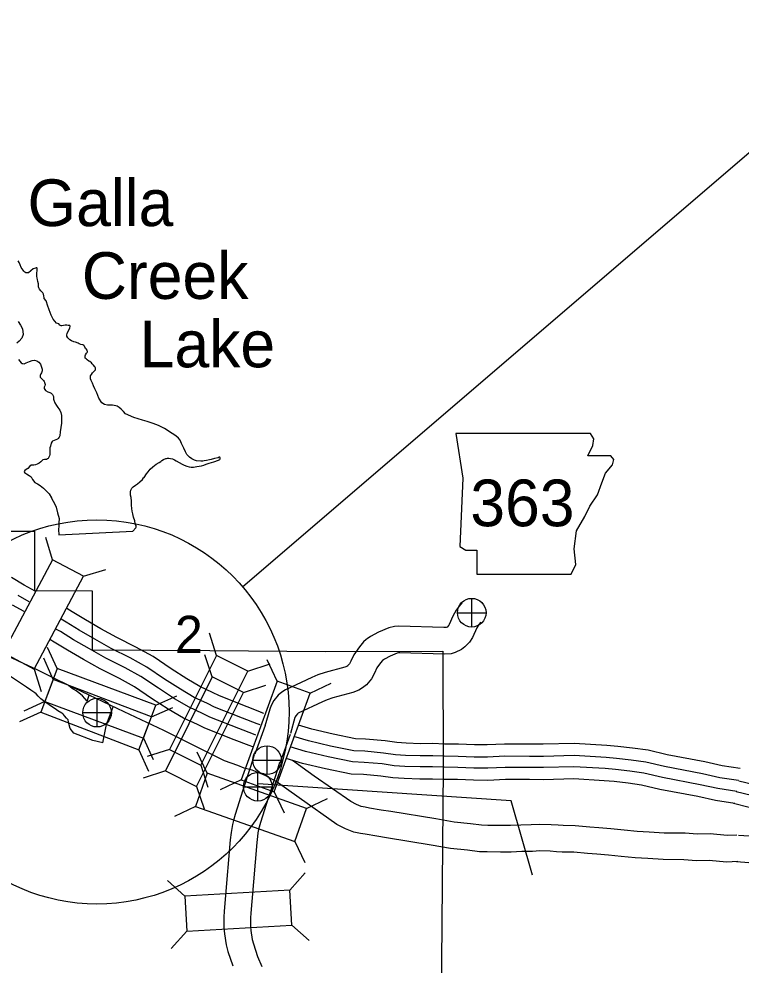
# Model space of a CAD drawing. Extents: x 1374139 to 1377472, y 1168351 to 1170484.
# Drawn here: x 1374655.3 to 1374736.9, y 1169975.1 to 1170082.1 of the extents above; entities that cross this region are included whole.
import ezdxf

# ---------------------------------------------------------------- set-up
doc = ezdxf.new("R2010")
doc.units = 0
doc.layers.add('15', color=7, linetype='Continuous')
doc.layers.add('Default', color=7, linetype='Continuous')

msp = doc.modelspace()

# ---------------------------------------------------------------- linework, layer by layer
at = {"layer": '15'}
msp.add_line((1374910.7, 1170215.21), (1374680.58, 1170017.86), dxfattribs=at)
msp.add_circle((1374664.1, 1170003.73), 21.71, dxfattribs=at)
at = {"layer": 'Default'}
for p, q in [((1374659.09, 1170020.93), (1374658.32, 1170023.46)), ((1374662.59, 1170019.07), (1374665.11, 1170019.84)), ((1374706.46, 1170013.33), (1374706.46, 1170016.58)), ((1374704.84, 1170014.95), (1374708.09, 1170014.95)), ((1374677.63, 1170010.11), (1374676.81, 1170012.62)), ((1374659.61, 1170008.63), (1374658.51, 1170011.03)), ((1374659.16, 1170007.41), (1374658.09, 1170009.82)), ((1374677.14, 1170007.69), (1374676.31, 1170010.2)), ((1374684.47, 1170007.22), (1374683.35, 1170009.61)), ((1374657.01, 1170008.58), (1374657.78, 1170006.06)), ((1374681.17, 1170008.33), (1374683.68, 1170009.16)), ((1374680.68, 1170005.92), (1374683.19, 1170006.76)), ((1374688.19, 1170005.87), (1374690.58, 1170006.99)), ((1374664.11, 1170002.03), (1374664.11, 1170005.28)), ((1374670.74, 1170004.48), (1374673.14, 1170005.57)), ((1374658.22, 1170004.92), (1374655.82, 1170003.82)), ((1374670.26, 1170003.16), (1374672.67, 1170004.24)), ((1374657.75, 1170003.71), (1374655.34, 1170002.63)), ((1374662.49, 1170003.65), (1374665.74, 1170003.65)), ((1374669.36, 1170000.77), (1374670.45, 1169998.36)), ((1374683.33, 1169996.65), (1374683.33, 1169999.9)), ((1374668.84, 1169999.46), (1374669.92, 1169997.05)), ((1374672.29, 1169999.5), (1374669.78, 1169998.68)), ((1374676.57, 1169996.8), (1374675.44, 1169999.18)), ((1374681.7, 1169998.28), (1374684.95, 1169998.28)), ((1374671.83, 1169997.07), (1374669.32, 1169996.24)), ((1374675.83, 1169997.72), (1374676.65, 1169995.22)), ((1374682.28, 1169993.66), (1374682.28, 1169996.91)), ((1374680.41, 1169996.06), (1374678.02, 1169994.94)), ((1374675.37, 1169995.3), (1374676.2, 1169992.79)), ((1374680.66, 1169995.28), (1374683.91, 1169995.28)), ((1374684.14, 1169994.7), (1374685.25, 1169992.31)), ((1374687.77, 1169992.83), (1374690.15, 1169993.96)), ((1374675.25, 1169993.06), (1374672.87, 1169991.93)), ((1374686.45, 1169989.09), (1374687.58, 1169986.71)), ((1374685.89, 1169983.59), (1374687.65, 1169985.56)), ((1374674.03, 1169982.92), (1374672.06, 1169984.68)), ((1374686.12, 1169979.63), (1374688.09, 1169977.88)), ((1374674.26, 1169978.96), (1374672.5, 1169976.99))]:
    msp.add_line(p, q, dxfattribs=at)
for points in [[(1374657.35, 1170053.58), (1374657.34, 1170053.71), (1374657.36, 1170053.8), (1374657.35, 1170053.88), (1374657.29, 1170053.92), (1374657.21, 1170053.93), (1374657.16, 1170053.91), (1374656.88, 1170053.81), (1374656.37, 1170053.37), (1374656.3, 1170053.35), (1374656.16, 1170053.35), (1374656.05, 1170053.38), (1374655.94, 1170053.43), (1374655.84, 1170053.54), (1374655.75, 1170053.68), (1374655.55, 1170053.97), (1374655.43, 1170054.29), (1374655.31, 1170054.55), (1374655.2, 1170054.74)], [(1374666.06, 1170038.38), (1374665.86, 1170038.42), (1374665.55, 1170038.42), (1374665.31, 1170038.41), (1374664.97, 1170038.5), (1374664.65, 1170038.67), (1374664.33, 1170039.21), (1374664.08, 1170039.79), (1374663.85, 1170040.24), (1374663.7, 1170040.6), (1374663.58, 1170040.89), (1374663.44, 1170041.18), (1374663.38, 1170041.4), (1374663.38, 1170041.71), (1374663.47, 1170041.89), (1374663.58, 1170042.07), (1374663.65, 1170042.12), (1374663.72, 1170042.18), (1374663.78, 1170042.25), (1374663.84, 1170042.3), (1374663.9, 1170042.38), (1374663.92, 1170042.42), (1374663.95, 1170042.52), (1374663.94, 1170042.64), (1374663.88, 1170042.71), (1374663.85, 1170042.74), (1374663.7, 1170042.92), (1374663.62, 1170043), (1374663.55, 1170043.1), (1374663.48, 1170043.2), (1374663.29, 1170043.33), (1374663.18, 1170043.39), (1374663.01, 1170043.53), (1374662.87, 1170043.65), (1374662.78, 1170043.74), (1374662.77, 1170043.84), (1374662.78, 1170043.99), (1374662.8, 1170044.11), (1374662.9, 1170044.27), (1374662.99, 1170044.35), (1374663.03, 1170044.45), (1374662.99, 1170044.64), (1374662.88, 1170044.79), (1374662.82, 1170044.86), (1374662.74, 1170044.98), (1374662.69, 1170045.07), (1374662.6, 1170045.16), (1374662.51, 1170045.22), (1374662.27, 1170045.28), (1374662.09, 1170045.34), (1374661.98, 1170045.43), (1374661.68, 1170045.53), (1374661.48, 1170045.58), (1374661.23, 1170045.67), (1374661.05, 1170045.78), (1374660.92, 1170045.89), (1374660.79, 1170046.01), (1374660.68, 1170046.2), (1374660.68, 1170046.34), (1374660.74, 1170046.56), (1374660.99, 1170047.03), (1374661.04, 1170047.15), (1374661.08, 1170047.29), (1374661.04, 1170047.4), (1374660.93, 1170047.42), (1374660.83, 1170047.43), (1374660.71, 1170047.44), (1374660.51, 1170047.44), (1374660.33, 1170047.4), (1374660.12, 1170047.38), (1374660.04, 1170047.39), (1374659.91, 1170047.47), (1374659.8, 1170047.59), (1374659.52, 1170047.69), (1374659.32, 1170047.9), (1374659.14, 1170048.12), (1374658.93, 1170048.6), (1374658.69, 1170049.2), (1374658.52, 1170049.73), (1374658.4, 1170050.08), (1374658.36, 1170050.22), (1374658.15, 1170050.48), (1374658.13, 1170050.56), (1374658.09, 1170050.75), (1374658.05, 1170050.95), (1374657.99, 1170051.11), (1374657.91, 1170051.19), (1374657.86, 1170051.22), (1374657.74, 1170051.35), (1374657.61, 1170051.52), (1374657.54, 1170051.68), (1374657.51, 1170051.78), (1374657.48, 1170052.02), (1374657.48, 1170052.14), (1374657.43, 1170052.39), (1374657.37, 1170052.62), (1374657.34, 1170052.78), (1374657.31, 1170052.98), (1374657.3, 1170053.23), (1374657.3, 1170053.38), (1374657.35, 1170053.58)], [(1374655.18, 1170047.87), (1374655.45, 1170047.47), (1374655.67, 1170047.02), (1374655.76, 1170046.41), (1374655.61, 1170046), (1374655.31, 1170045.65), (1374655.03, 1170045.43)], [(1374655.22, 1170043.56), (1374655.37, 1170043.39), (1374655.54, 1170043.2), (1374655.64, 1170043.13), (1374655.73, 1170043.11), (1374655.87, 1170043.1), (1374656.11, 1170043.2), (1374656.49, 1170043.35), (1374656.79, 1170043.46), (1374657.04, 1170043.48), (1374657.32, 1170043.42), (1374657.52, 1170043.28), (1374657.7, 1170043.03), (1374657.78, 1170042.83), (1374657.89, 1170042.47), (1374657.89, 1170042.3), (1374657.83, 1170042.08), (1374657.76, 1170041.94), (1374657.69, 1170041.78), (1374657.67, 1170041.72), (1374657.67, 1170041.64), (1374657.69, 1170041.56), (1374657.78, 1170041.45), (1374657.89, 1170041.36), (1374658.05, 1170041.21), (1374658.13, 1170041.09), (1374658.16, 1170041.02), (1374658.18, 1170040.99), (1374658.22, 1170040.84), (1374658.23, 1170040.75), (1374658.19, 1170040.61), (1374658.14, 1170040.44), (1374658.13, 1170040.37), (1374658.14, 1170040.31), (1374658.22, 1170040.17), (1374658.29, 1170040.08), (1374658.54, 1170039.93), (1374658.78, 1170039.83), (1374658.91, 1170039.76), (1374659.08, 1170039.63), (1374659.18, 1170039.4), (1374659.19, 1170039.22), (1374659.2, 1170039.08), (1374659.22, 1170038.96), (1374659.35, 1170038.67), (1374659.52, 1170038.38), (1374659.69, 1170038.15), (1374659.89, 1170037.83), (1374660.02, 1170037.59), (1374660.11, 1170037.24), (1374660.08, 1170036.37), (1374659.95, 1170035.38), (1374659.9, 1170034.96), (1374659.82, 1170034.78), (1374659.71, 1170034.65), (1374659.63, 1170034.57), (1374659.45, 1170034.49), (1374659.26, 1170034.41), (1374659.09, 1170034.34), (1374659.02, 1170034.29), (1374658.94, 1170034.13), (1374658.84, 1170033.79), (1374658.79, 1170033.58), (1374658.78, 1170033.37), (1374658.76, 1170033.05), (1374658.76, 1170032.85), (1374658.74, 1170032.7), (1374658.67, 1170032.52), (1374658.57, 1170032.38), (1374658.5, 1170032.33), (1374658.38, 1170032.28), (1374658.28, 1170032.26)], [(1374635.04, 1170037.43), (1374636.08, 1170037.43), (1374636.01, 1170037.28), (1374637.38, 1170036.89), (1374637.59, 1170037.42), (1374643.93, 1170037.4), (1374650.53, 1170037.38), (1374650.48, 1170030.78), (1374650.43, 1170024.18), (1374657.03, 1170024.15), (1374657.04, 1170017.47)], [(1374668.16, 1170024.17), (1374668.5, 1170024.55), (1374668.53, 1170024.6), (1374668.53, 1170024.69), (1374668.52, 1170024.81), (1374668.43, 1170024.99), (1374668.37, 1170025.34), (1374668.22, 1170025.73), (1374668.16, 1170026.11), (1374668.09, 1170026.43), (1374668.06, 1170026.73), (1374668.01, 1170027.11), (1374667.99, 1170027.54), (1374667.95, 1170027.98), (1374667.91, 1170028.24), (1374667.91, 1170028.47), (1374667.9, 1170028.63), (1374667.93, 1170028.81), (1374668.03, 1170029.01), (1374668.21, 1170029.18), (1374668.46, 1170029.37), (1374668.7, 1170029.52), (1374668.96, 1170029.73), (1374669.24, 1170030), (1374669.37, 1170030.19), (1374669.42, 1170030.25), (1374669.69, 1170030.63), (1374669.88, 1170030.89), (1374670.11, 1170031.19), (1374670.41, 1170031.44), (1374670.61, 1170031.59), (1374670.81, 1170031.73), (1374671.12, 1170031.93), (1374671.33, 1170032.06), (1374671.45, 1170032.16), (1374671.63, 1170032.27), (1374671.88, 1170032.37), (1374671.97, 1170032.39), (1374672.09, 1170032.41), (1374672.24, 1170032.42), (1374672.42, 1170032.38), (1374672.64, 1170032.34), (1374672.87, 1170032.23), (1374673.07, 1170032.13), (1374673.39, 1170031.94), (1374673.72, 1170031.75), (1374673.95, 1170031.64), (1374674.26, 1170031.51), (1374674.51, 1170031.44), (1374674.76, 1170031.41), (1374675.02, 1170031.41), (1374675.39, 1170031.47), (1374675.66, 1170031.5), (1374675.9, 1170031.56), (1374676.18, 1170031.63), (1374676.45, 1170031.73), (1374676.78, 1170031.84), (1374677.05, 1170031.92), (1374677.3, 1170032.02), (1374677.44, 1170032.05), (1374677.71, 1170032.14), (1374677.85, 1170032.18), (1374677.99, 1170032.26), (1374678.04, 1170032.35), (1374678.04, 1170032.44), (1374677.98, 1170032.52), (1374677.93, 1170032.52), (1374677.8, 1170032.47), (1374677.4, 1170032.38), (1374677.02, 1170032.28), (1374676.81, 1170032.22), (1374676.49, 1170032.16), (1374676.23, 1170032.1), (1374676.06, 1170032.08), (1374675.84, 1170032.08), (1374675.36, 1170032.12), (1374675.11, 1170032.18), (1374674.82, 1170032.35), (1374674.56, 1170032.52), (1374674.26, 1170032.82), (1374674.1, 1170033.13), (1374673.92, 1170033.53), (1374673.81, 1170033.79), (1374673.67, 1170034.08), (1374673.5, 1170034.44), (1374673.31, 1170034.69), (1374673.01, 1170034.95), (1374672.59, 1170035.22), (1374671.75, 1170035.77), (1374671.07, 1170036.1), (1374670.45, 1170036.34), (1374669.78, 1170036.55), (1374669.25, 1170036.73), (1374668.28, 1170037), (1374667.34, 1170037.44), (1374667.1, 1170037.71), (1374666.85, 1170037.96), (1374666.61, 1170038.16), (1374666.4, 1170038.28), (1374666.23, 1170038.32), (1374666.06, 1170038.38)], [(1374658.28, 1170032.26), (1374658.16, 1170032.26), (1374658.03, 1170032.23), (1374657.98, 1170032.22), (1374657.9, 1170032.17), (1374657.74, 1170032), (1374657.57, 1170031.85), (1374657.36, 1170031.73), (1374657.14, 1170031.65), (1374656.96, 1170031.63), (1374656.82, 1170031.63), (1374656.68, 1170031.62), (1374656.5, 1170031.5), (1374656.28, 1170031.26), (1374656.09, 1170031.13), (1374655.94, 1170031.03), (1374655.88, 1170030.9), (1374655.91, 1170030.78), (1374656.12, 1170030.63), (1374656.44, 1170030.47), (1374656.65, 1170030.31), (1374656.81, 1170030), (1374657.06, 1170029.68), (1374657.38, 1170029.51), (1374657.67, 1170029.31), (1374658.05, 1170029.01), (1374658.41, 1170028.7), (1374658.68, 1170028.38), (1374658.96, 1170027.93), (1374658.97, 1170027.91), (1374659.16, 1170027.57), (1374659.35, 1170027.23), (1374659.5, 1170026.88), (1374659.65, 1170026.23), (1374659.81, 1170025.59), (1374659.8, 1170025.11), (1374659.78, 1170024.73), (1374659.76, 1170024.37), (1374659.78, 1170023.75)], [(1374659.78, 1170023.75), (1374668.16, 1170024.17)], [(1374657.1, 1170017.38), (1374655.87, 1170018.08), (1374654.44, 1170018.91)], [(1374657.04, 1170017.47), (1374663.55, 1170017.44), (1374663.54, 1170010.76), (1374676.85, 1170010.66), (1374689.94, 1170010.57), (1374703.21, 1170010.61), (1374703.24, 1169997.37), (1374703.01, 1169971.08), (1374689.77, 1169970.99), (1374683.16, 1169970.99), (1374683.1, 1169957.78), (1374683.06, 1169951.17), (1374676.42, 1169951.17), (1374676.38, 1169944.56), (1374676.11, 1169917.93), (1374669.48, 1169917.94)], [(1374656.44, 1170016.18), (1374655.19, 1170016.88)], [(1374705.39, 1170016.01), (1374704.97, 1170015.59), (1374704.72, 1170015.25), (1374704.34, 1170014.55), (1374703.92, 1170013.6), (1374703.88, 1170013.54), (1374703.68, 1170013.33), (1374703.68, 1170013.33), (1374703.57, 1170013.28), (1374703.32, 1170013.26), (1374698.24, 1170013.44), (1374697.72, 1170013.39), (1374697.09, 1170013.25), (1374695.94, 1170012.76), (1374695.02, 1170012.26), (1374694.64, 1170012)], [(1374655.87, 1170015.07), (1374654.57, 1170015.8)], [(1374682.71, 1170003.67), (1374681.07, 1170004.3), (1374677.94, 1170005.55), (1374677.17, 1170005.94), (1374675.73, 1170006.59), (1374674.26, 1170007.47), (1374672.48, 1170008.6), (1374670.44, 1170009.98), (1374668.51, 1170011.05), (1374666.35, 1170012.14), (1374664.55, 1170013.14), (1374662.81, 1170014.14), (1374661.31, 1170015.06), (1374660.71, 1170015.41)], [(1374682.22, 1170002.38), (1374680.57, 1170003.01), (1374677.38, 1170004.29), (1374676.58, 1170004.7), (1374675.09, 1170005.37), (1374673.54, 1170006.3), (1374671.72, 1170007.45), (1374669.72, 1170008.81), (1374667.87, 1170009.84), (1374665.71, 1170010.92), (1374663.87, 1170011.94), (1374662.1, 1170012.96), (1374660.61, 1170013.88), (1374660.04, 1170014.21)], [(1374707.5, 1170013.88), (1374707.25, 1170013.62), (1374707.04, 1170013.23), (1374706.55, 1170012.13), (1374706.2, 1170011.62), (1374705.7, 1170011.11), (1374705.29, 1170010.78), (1374704.6, 1170010.45), (1374704.12, 1170010.31), (1374703.36, 1170010.26), (1374698.32, 1170010.43), (1374698.2, 1170010.42), (1374698.02, 1170010.38), (1374697.24, 1170010.05), (1374696.61, 1170009.71), (1374696.38, 1170009.55)], [(1374681.78, 1170001.22), (1374680.12, 1170001.85), (1374676.86, 1170003.15), (1374676.04, 1170003.57), (1374674.51, 1170004.26), (1374672.88, 1170005.23), (1374671.04, 1170006.41), (1374669.07, 1170007.74), (1374667.28, 1170008.73), (1374665.12, 1170009.82), (1374663.26, 1170010.85), (1374661.46, 1170011.89), (1374659.97, 1170012.81), (1374659.45, 1170013.1)], [(1374681.29, 1169999.93), (1374679.61, 1170000.57), (1374676.3, 1170001.9), (1374675.45, 1170002.33), (1374673.87, 1170003.04), (1374672.16, 1170004.06), (1374670.28, 1170005.26), (1374668.35, 1170006.57), (1374666.64, 1170007.52), (1374664.48, 1170008.6), (1374662.58, 1170009.65), (1374660.76, 1170010.71), (1374659.26, 1170011.63), (1374658.78, 1170011.91)], [(1374694.64, 1170012), (1374694.53, 1170011.92), (1374694.23, 1170011.65), (1374693.76, 1170011.11), (1374693.13, 1170010.18), (1374692.8, 1170009.46), (1374692.65, 1170009.18), (1374692.43, 1170008.93), (1374692.41, 1170008.91), (1374692.11, 1170008.79), (1374689.9, 1170008.19), (1374689.05, 1170007.91), (1374688.38, 1170007.63), (1374685.42, 1170006.24), (1374684.98, 1170005.97), (1374684.6, 1170005.61), (1374684.11, 1170005.04), (1374683.79, 1170004.47), (1374683.63, 1170004.06), (1374683.07, 1170002.11)], [(1374678.5, 1169998.21), (1374671.65, 1170001.64), (1374667.18, 1170003.74), (1374663.21, 1170005.63), (1374659.67, 1170007.34), (1374657.25, 1170008.54), (1374655.3, 1170009.43), (1374653.28, 1170010.43)], [(1374696.41, 1170009.57), (1374696.38, 1170009.54), (1374696.15, 1170009.28), (1374695.75, 1170008.7), (1374695.48, 1170008.11), (1374695.14, 1170007.48), (1374694.55, 1170006.78), (1374694.13, 1170006.44), (1374693.71, 1170006.19), (1374693.03, 1170005.93), (1374690.77, 1170005.32), (1374690.11, 1170005.1), (1374689.6, 1170004.88), (1374686.86, 1170003.6), (1374686.83, 1170003.58), (1374686.77, 1170003.53), (1374686.58, 1170003.31), (1374686.5, 1170003.17), (1374686.47, 1170003.1), (1374685.96, 1170001.29)], [(1374664.76, 1170000.24), (1374663.62, 1170000.49), (1374661.5, 1170001.34), (1374661.09, 1170001.85), (1374660.91, 1170002.44), (1374660.89, 1170002.6), (1374660.84, 1170002.85), (1374660.65, 1170003.04), (1374660.43, 1170003.31), (1374660.33, 1170003.44), (1374660.25, 1170003.5), (1374660.12, 1170003.59), (1374659.69, 1170003.86), (1374659.39, 1170004.1), (1374659.06, 1170004.29), (1374658.69, 1170004.54), (1374658.2, 1170004.86), (1374657.76, 1170005.22), (1374657.47, 1170005.53), (1374657.22, 1170005.77), (1374657.07, 1170005.9), (1374656.62, 1170006.19), (1374656.15, 1170006.52), (1374654.33, 1170007.74)], [(1374661.5, 1170006.27), (1374661.28, 1170006.4), (1374660.88, 1170006.71)], [(1374662.98, 1170004.95), (1374662.46, 1170005.56), (1374662.06, 1170005.9), (1374661.75, 1170006.11), (1374661.5, 1170006.27)], [(1374662.98, 1170004.95), (1374663.23, 1170005.63)], [(1374664.76, 1170000.24), (1374665.18, 1170002.31), (1374665.71, 1170003.69), (1374665.94, 1170004.31)], [(1374682.98, 1170003.57), (1374682.68, 1170003.68)], [(1374683.1, 1170002.2), (1374681.95, 1169998.94)], [(1374682.55, 1170002.27), (1374682.21, 1170002.39)], [(1374736.82, 1169997.33), (1374734.76, 1169997.64), (1374732.82, 1169998.08), (1374728.56, 1169998.89), (1374726.41, 1169999.4), (1374724.65, 1169999.65), (1374722.97, 1169999.83), (1374721.75, 1169999.95), (1374718.06, 1170000.17), (1374714.55, 1170000.07), (1374713.02, 1170000.08), (1374710.18, 1170000.1), (1374708.21, 1170000), (1374706.76, 1170000.01), (1374704.96, 1170000.08), (1374703.39, 1170000.1), (1374702.07, 1170000.15), (1374700.66, 1170000.14), (1374699.04, 1170000.19), (1374697.99, 1170000.26), (1374696.66, 1170000.46), (1374694.47, 1170000.65), (1374693.31, 1170000.69), (1374690.8, 1170001.21), (1374688.37, 1170001.79), (1374686.87, 1170002.24)], [(1374682.04, 1170001.12), (1374681.79, 1170001.21)], [(1374685.93, 1170001.2), (1374684.78, 1169997.94)], [(1374681.71, 1169999.78), (1374681.32, 1169999.92)], [(1374736.61, 1169995.97), (1374734.51, 1169996.29), (1374732.54, 1169996.74), (1374728.27, 1169997.55), (1374726.15, 1169998.05), (1374724.47, 1169998.28), (1374722.83, 1169998.47), (1374721.64, 1169998.57), (1374718.04, 1169998.8), (1374714.57, 1169998.69), (1374713.01, 1169998.71), (1374710.21, 1169998.72), (1374708.25, 1169998.62), (1374706.73, 1169998.63), (1374704.93, 1169998.7), (1374703.36, 1169998.72), (1374702.05, 1169998.77), (1374700.64, 1169998.76), (1374698.97, 1169998.81), (1374697.84, 1169998.9), (1374696.5, 1169999.09), (1374694.39, 1169999.28), (1374693.14, 1169999.32), (1374690.5, 1169999.87), (1374688.01, 1170000.46), (1374686.36, 1170000.95)], [(1374681.87, 1169998.89), (1374681.45, 1169997.52), (1374680.6, 1169994.89), (1374679.72, 1169992.12), (1374679.52, 1169991.45), (1374679.43, 1169991.02), (1374679.35, 1169990.57), (1374679.26, 1169990.09), (1374679.17, 1169989.28), (1374678.6, 1169982.58), (1374678.48, 1169981.19), (1374678.45, 1169980.58), (1374678.44, 1169979.94), (1374678.46, 1169979.31), (1374678.51, 1169978.66), (1374678.71, 1169977.41), (1374678.9, 1169976.65), (1374679.45, 1169975.03)], [(1374736.42, 1169994.74), (1374734.27, 1169995.06), (1374732.29, 1169995.51), (1374728.01, 1169996.32), (1374725.92, 1169996.82), (1374724.32, 1169997.04), (1374722.7, 1169997.22), (1374721.55, 1169997.33), (1374718.02, 1169997.54), (1374714.58, 1169997.44), (1374713, 1169997.46), (1374710.24, 1169997.47), (1374708.27, 1169997.37), (1374706.7, 1169997.38), (1374704.9, 1169997.45), (1374703.33, 1169997.48), (1374702.03, 1169997.52), (1374700.63, 1169997.51), (1374698.9, 1169997.56), (1374697.7, 1169997.65), (1374696.35, 1169997.85), (1374694.31, 1169998.03), (1374692.99, 1169998.08), (1374690.23, 1169998.65), (1374687.69, 1169999.25), (1374685.93, 1169999.78)], [(1374684.36, 1169995.86), (1374683.93, 1169996.1), (1374683.13, 1169996.54), (1374682.4, 1169996.85), (1374681.66, 1169997.15), (1374680.75, 1169997.37), (1374680.03, 1169997.67), (1374678.5, 1169998.21)], [(1374684.74, 1169998.03), (1374684.32, 1169996.63), (1374683.46, 1169993.97), (1374682.58, 1169991.24), (1374682.43, 1169990.71), (1374682.37, 1169990.44), (1374682.3, 1169990.06), (1374682.24, 1169989.67), (1374682.16, 1169988.99), (1374681.59, 1169982.32), (1374681.48, 1169980.97), (1374681.44, 1169980.46), (1374681.44, 1169979.98), (1374681.46, 1169979.48), (1374681.49, 1169979.01), (1374681.65, 1169978.02), (1374681.78, 1169977.51), (1374682.26, 1169976.08), (1374682.73, 1169974.94)], [(1374736.22, 1169993.38), (1374734.02, 1169993.71), (1374732.01, 1169994.16), (1374727.72, 1169994.98), (1374725.67, 1169995.46), (1374724.15, 1169995.68), (1374722.56, 1169995.85), (1374721.44, 1169995.96), (1374717.99, 1169996.17), (1374714.59, 1169996.07), (1374712.99, 1169996.08), (1374710.27, 1169996.1), (1374708.3, 1169996), (1374706.66, 1169996.01), (1374704.86, 1169996.08), (1374703.29, 1169996.1), (1374702.01, 1169996.14), (1374700.61, 1169996.14), (1374698.83, 1169996.19), (1374697.55, 1169996.29), (1374696.19, 1169996.48), (1374694.22, 1169996.66), (1374692.83, 1169996.71), (1374689.93, 1169997.31), (1374687.33, 1169997.92), (1374685.48, 1169998.48)], [(1374736.43, 1169989.8), (1374735.34, 1169989.76), (1374733.42, 1169989.95), (1374731.96, 1169989.92), (1374730.58, 1169990.03), (1374728.21, 1169990.04), (1374726.52, 1169990.15), (1374725.16, 1169990.22), (1374723.68, 1169990.36), (1374722.2, 1169990.52), (1374720.84, 1169990.63), (1374719.81, 1169990.72), (1374718.17, 1169990.86), (1374716.79, 1169990.89), (1374716.24, 1169990.92), (1374715.46, 1169990.97), (1374714.1, 1169991.02), (1374713.18, 1169990.96), (1374712.03, 1169990.94), (1374710.86, 1169990.88), (1374709.72, 1169990.88), (1374708.28, 1169990.9), (1374707.58, 1169990.92), (1374706.32, 1169991.08), (1374704.48, 1169991.26), (1374702.4, 1169991.65), (1374697.31, 1169992.47), (1374696.23, 1169992.64), (1374694.92, 1169992.87), (1374694.43, 1169992.95), (1374693.98, 1169993.04), (1374693.44, 1169993.25), (1374692.78, 1169993.59), (1374688.67, 1169996.47), (1374686.19, 1169998.25)], [(1374736.56, 1169986.81), (1374735.26, 1169986.75), (1374733.3, 1169986.95), (1374731.88, 1169986.91), (1374730.45, 1169987.03), (1374728.1, 1169987.04), (1374726.35, 1169987.15), (1374724.94, 1169987.23), (1374723.37, 1169987.38), (1374721.91, 1169987.54), (1374720.59, 1169987.64), (1374719.55, 1169987.73), (1374718, 1169987.87), (1374716.68, 1169987.89), (1374716.05, 1169987.93), (1374715.31, 1169987.98), (1374714.15, 1169988.02), (1374713.32, 1169987.96), (1374712.13, 1169987.94), (1374710.93, 1169987.88), (1374709.7, 1169987.88), (1374708.21, 1169987.9), (1374707.35, 1169987.92), (1374705.99, 1169988.1), (1374704.05, 1169988.29), (1374701.89, 1169988.69), (1374696.83, 1169989.5), (1374695.73, 1169989.68), (1374694.43, 1169989.91), (1374693.88, 1169990), (1374693.13, 1169990.15), (1374692.2, 1169990.51), (1374691.22, 1169991.02), (1374686.94, 1169994.02), (1374684.36, 1169995.86)], [(1374736.67, 1169995.96), (1374738.37, 1169995.54)], [(1374713.32, 1169985.29), (1374710.93, 1169993.68), (1374682.32, 1169995.62)], [(1374736.37, 1169994.75), (1374738.1, 1169994.32)], [(1374736.04, 1169993.41), (1374737.81, 1169992.97)], [(1374736.6, 1169989.8), (1374737.82, 1169989.72), (1374738.97, 1169989.77), (1374740.12, 1169989.85), (1374740.74, 1169989.9), (1374742.64, 1169990.13), (1374743.52, 1169990.25), (1374744.49, 1169990.39), (1374745.86, 1169990.69), (1374747.16, 1169990.94), (1374747.63, 1169991.05), (1374748.24, 1169991.26), (1374749.37, 1169991.54), (1374749.81, 1169991.66)], [(1374736.4, 1169986.81), (1374737.79, 1169986.72)]]:
    msp.add_lwpolyline(points, dxfattribs=at)
for points in [[(1374704.68, 1170035.21), (1374705.44, 1170030.14), (1374705.1, 1170022.44), (1374705.78, 1170022.01), (1374707.05, 1170022.01), (1374707.05, 1170019.31), (1374717.71, 1170019.31), (1374718.22, 1170020.41), (1374718.05, 1170022.18), (1374718.3, 1170024.21), (1374719.23, 1170025.82), (1374719.82, 1170027.01), (1374720.67, 1170028.27), (1374721.18, 1170029.63), (1374721.6, 1170030.73), (1374722.36, 1170031.66), (1374722.53, 1170032.25), (1374722.19, 1170032.67), (1374719.57, 1170032.67), (1374720.16, 1170033.86), (1374720.25, 1170034.62), (1374719.89, 1170035.2)], [(1374657.01, 1170008.58), (1374662.59, 1170019.07), (1374659.09, 1170020.93), (1374653.51, 1170010.44)], [(1374675.83, 1169997.72), (1374681.17, 1170008.33), (1374677.63, 1170010.11), (1374672.29, 1169999.5)], [(1374658.22, 1170004.92), (1374669.36, 1170000.77), (1374670.74, 1170004.48), (1374659.61, 1170008.63)], [(1374657.75, 1170003.71), (1374668.84, 1169999.46), (1374670.26, 1170003.16), (1374659.16, 1170007.41)], [(1374675.37, 1169995.3), (1374680.68, 1170005.92), (1374677.14, 1170007.69), (1374671.83, 1169997.07)], [(1374684.14, 1169994.7), (1374688.19, 1170005.87), (1374684.47, 1170007.22), (1374680.41, 1169996.06)], [(1374675.25, 1169993.06), (1374686.45, 1169989.09), (1374687.77, 1169992.83), (1374676.57, 1169996.8)], [(1374674.26, 1169978.96), (1374686.12, 1169979.63), (1374685.89, 1169983.59), (1374674.03, 1169982.92)]]:
    msp.add_lwpolyline(points, close=True, dxfattribs=at)
for centre in [(1374706.46, 1170014.95), (1374664.11, 1170003.65), (1374683.33, 1169998.28), (1374682.28, 1169995.28)]:
    msp.add_circle(centre, 1.62, dxfattribs=at)

# ---------------------------------------------------------------- texts
for s, height, p in [('Galla', 5.28, (1374656.25, 1170058.65)), ('Creek', 5.28, (1374662.39, 1170050.42)), ('Lake', 5.28, (1374668.93, 1170042.69)), ('363', 5.28, (1374706.3, 1170024.72)), ('2', 4.22, (1374672.92, 1170010.38))]:
    msp.add_text(s, height=height, dxfattribs=at).set_placement(p)

doc.saveas('drawing.dxf')
